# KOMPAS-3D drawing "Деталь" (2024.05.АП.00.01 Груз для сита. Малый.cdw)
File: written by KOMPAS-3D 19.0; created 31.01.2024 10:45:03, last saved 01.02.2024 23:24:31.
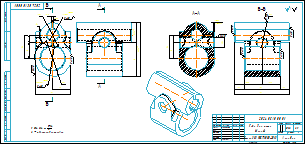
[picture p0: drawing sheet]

Sheet 1: A4x3, landscape

Document properties: Автор: mail.maksim@mail.ru; Знак неуказанной шероховатости: 6; Масса: 0.322187; Форматы листов документа: A4@4~3; Полное имя файла: ..\2024.05.АП 3D модели\2024.05.АП.00.01 Груз для сита. Малый.m3d

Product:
- Part/product: Деталь
    Масса: 0.322187
  - Body: Тело 1
      Масса: 0.334992

Title block, sheet 1: Наименование: Груз для сита. / Малый; designation: 2024.05.АП.00.01; Материал: Сталь 35Л ГОСТ 1050-2013; Масса: 0,32; Количество листов документа: 1; organisation: АгроПак; Форматы листов документа: A4 3; Разработал: Полынский; Утвердил: Гордиенко

Views: Спереди 1
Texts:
  Rz20
Dimensions and other numbers on the sheet: 25,15; 12; 26; 2,5; 1,25; 38; 36; 1; 24; 8; 16; 10; 57; 37; 18,5; 28,5; 18; 35; 20,94; 55,94; 6 фасок; 2:1; 0,32; 2024.05.АП.00.01; 2024.05.АП.00.01-

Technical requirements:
  * - Размеры для справки.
